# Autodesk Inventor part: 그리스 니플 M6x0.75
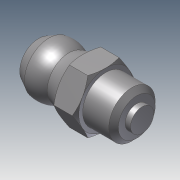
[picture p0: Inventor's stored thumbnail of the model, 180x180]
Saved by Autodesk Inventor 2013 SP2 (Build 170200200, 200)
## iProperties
Created: 2025-04
Part Number: 그리스 니플 M6x0.75
Material: Generic
Document SubType Name: Modeling
Designer: i
Density: 1 g/cm^3
Author: i
변환 표준: STEP AP214IS
전처리기: Build: 200, Release: 2013 SP2 Update 6 - Date: Thu 07/17/2014
전송 단위: 밀리미터
불확실성: 0.01
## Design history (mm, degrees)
node "그리스 니플 M6x0.751"
body "Solid1"
node "기준1"
